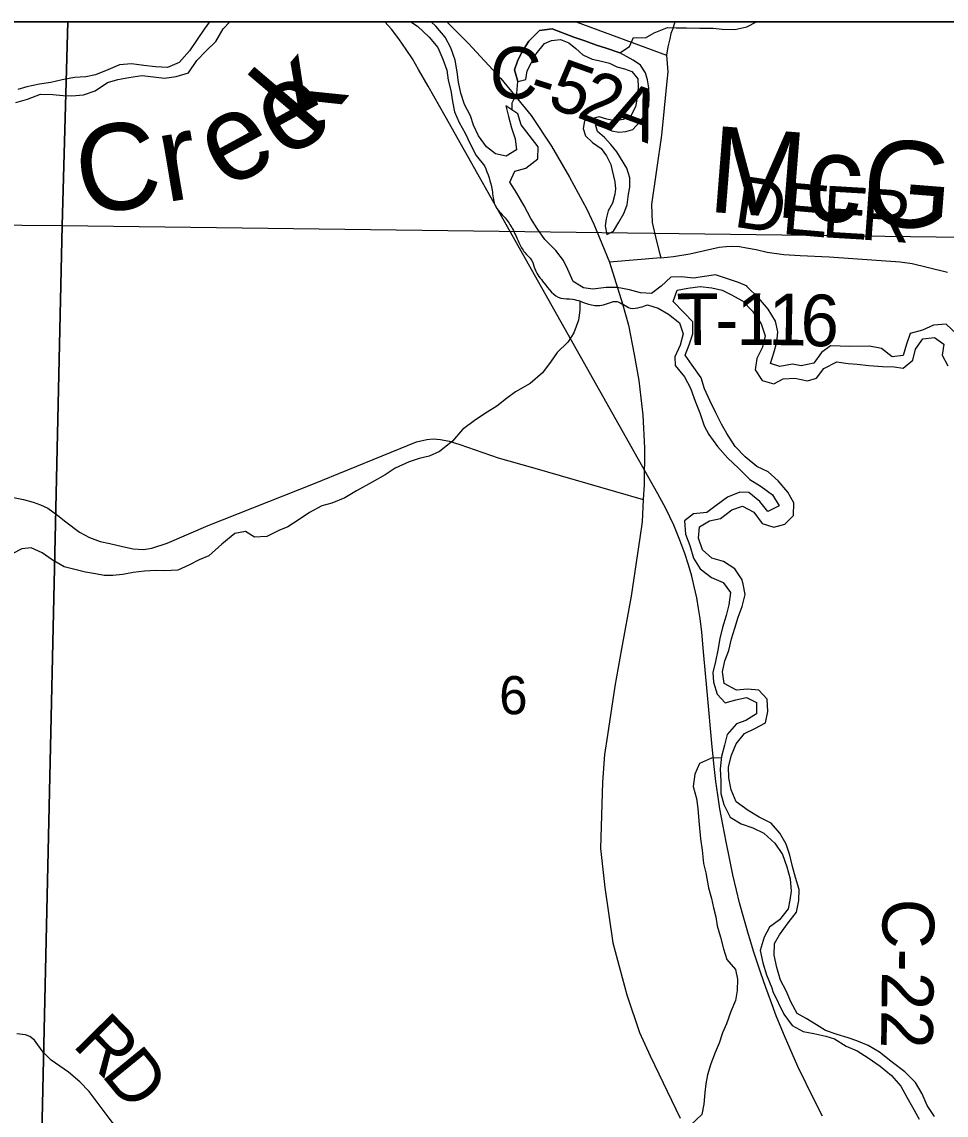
# Model space of a CAD drawing. Extents: x -1.2 to 34, y -8.5 to 22.
# Drawn here: x 4.454 to 5.468, y 19.699 to 20.9 of the extents above; entities that cross this region are included whole.
import ezdxf

# ---------------------------------------------------------------- set-up
doc = ezdxf.new("R2010")
doc.units = 0
for name, color, linetype in [('GM_X_County_Road', 7, 'Continuous'), ('GM_X_County_Road_Text', 7, 'Continuous'), ('GM_X_Major_River', 7, 'Continuous'), ('GM_X_Major_River_Text', 7, 'Continuous'), ('GM_X_Minor_Lake', 7, 'Continuous'), ('GM_X_Minor_River', 7, 'Continuous'), ('GM_X_Rail_Line', 7, 'Continuous'), ('GM_X_Section', 7, 'Continuous'), ('GM_X_Section_Text', 7, 'Continuous'), ('GM_X_State_Route', 7, 'Continuous'), ('GM_X_Township_Road', 7, 'Continuous'), ('GM_X_Township_Road_Text', 7, 'Continuous'), ('GM_X_Unincorporated_Text', 7, 'Continuous'), ('SH_Cut_Line', 7, 'Continuous'), ('SH_Data', 7, 'Continuous')]:
    doc.layers.add(name, color=color, linetype=linetype)

msp = doc.modelspace()

# ---------------------------------------------------------------- linework, layer by layer
at = {"layer": 'GM_X_County_Road'}
msp.add_line((5.0623, 20.9), (5.1613, 20.8632), dxfattribs=at)
for points in [[(5.1707, 20.9), (5.1707, 20.8998), (5.1681, 20.8917), (5.1663, 20.887), (5.1649, 20.8814), (5.1627, 20.8726), (5.1613, 20.8632), (5.1629, 20.8449), (5.1619, 20.8347), (5.156, 20.7754), (5.1449, 20.6994), (5.1458, 20.6794), (5.1503, 20.6592), (5.154, 20.6446)], [(5.154, 20.6446), (5.155, 20.6407), (5.0987, 20.6359)]]:
    msp.add_lwpolyline(points, dxfattribs=at)
at = {"layer": 'GM_X_Major_River'}
for points in [[(4.447, 20.8112), (4.4598, 20.8149), (4.4742, 20.8204), (4.4875, 20.8202), (4.4989, 20.8189), (4.5084, 20.8187), (4.5213, 20.8197), (4.5342, 20.8241), (4.5477, 20.8334), (4.5591, 20.8366), (4.5712, 20.8387), (4.5852, 20.8412), (4.5982, 20.8395), (4.6103, 20.8382), (4.6232, 20.84), (4.6365, 20.844), (4.6458, 20.8574), (4.6555, 20.8678), (4.6667, 20.8783), (4.6748, 20.8924), (4.6819, 20.9)], [(4.6598, 20.9), (4.6539, 20.8921), (4.6461, 20.8806), (4.6376, 20.8683), (4.6264, 20.8552), (4.6136, 20.8497), (4.6003, 20.8506), (4.5877, 20.8519), (4.574, 20.8539), (4.5607, 20.8526), (4.5482, 20.8474), (4.5346, 20.8419), (4.524, 20.8394), (4.5115, 20.8389), (4.4979, 20.8364), (4.4854, 20.8335), (4.4729, 20.8314), (4.4592, 20.8285), (4.4494, 20.8257)], [(4.8806, 20.9), (4.888, 20.8952), (4.9008, 20.8833), (4.9105, 20.8717), (4.916, 20.8589), (4.9204, 20.8468), (4.9217, 20.8359), (4.9246, 20.8245), (4.9263, 20.8124), (4.9288, 20.8011), (4.9339, 20.7894), (4.9402, 20.7778), (4.9461, 20.7653), (4.9524, 20.7533), (4.9617, 20.7417)], [(5.145, 20.6014), (5.1328, 20.6023), (5.1206, 20.6055), (5.1072, 20.608), (5.0951, 20.6081), (5.0807, 20.6064), (5.0704, 20.6077), (5.0589, 20.6147), (5.0529, 20.6279), (5.0482, 20.6377), (5.04, 20.6489), (5.0277, 20.6609), (5.0195, 20.6729), (5.0125, 20.6841), (5.005, 20.698), (4.9972, 20.7116), (4.9894, 20.724), (4.9949, 20.7358), (5.007, 20.7394), (5.0201, 20.7495), (5.0206, 20.7628), (5.0105, 20.7755), (5.002, 20.7868), (4.998, 20.7988), (4.9849, 20.8077), (4.9881, 20.796), (4.9914, 20.7835), (4.9954, 20.7715), (4.9967, 20.7594), (4.9855, 20.7523), (4.9736, 20.7548), (4.9636, 20.7626), (4.9551, 20.7746), (4.9495, 20.7866), (4.9463, 20.7968), (4.9397, 20.8092), (4.9356, 20.8217), (4.9332, 20.8338), (4.9314, 20.8451), (4.9293, 20.858), (4.9245, 20.8716), (4.9183, 20.8832), (4.9082, 20.8952), (4.9032, 20.9)], [(5.2501, 20.6096), (5.2406, 20.6136), (5.2283, 20.6176), (5.2153, 20.6219), (5.1911, 20.6185), (5.1777, 20.6198), (5.1663, 20.6196), (5.1555, 20.6095), (5.145, 20.6014)], [(5.2445, 20.287), (5.2363, 20.2991), (5.224, 20.3072), (5.2111, 20.3108), (5.201, 20.3201), (5.1966, 20.3329), (5.1976, 20.3451), (5.2085, 20.3517), (5.2206, 20.3542), (5.233, 20.3639), (5.2447, 20.3679), (5.2573, 20.3612), (5.2663, 20.3489), (5.2793, 20.3449), (5.2914, 20.3481), (5.3007, 20.3578), (5.3013, 20.3715), (5.2946, 20.3831), (5.2841, 20.3958), (5.273, 20.4055), (5.2607, 20.4114), (5.2476, 20.4221), (5.2368, 20.4333), (5.2278, 20.4476), (5.2219, 20.4578), (5.2156, 20.4705), (5.2089, 20.4841), (5.203, 20.4969), (5.1994, 20.509), (5.1896, 20.5228), (5.1819, 20.5337), (5.1862, 20.5452), (5.1902, 20.5574), (5.1904, 20.5703), (5.1803, 20.5807), (5.1687, 20.5927), (5.173, 20.6053), (5.1848, 20.6074), (5.1985, 20.6091), (5.211, 20.6078), (5.2225, 20.6053), (5.232, 20.6006), (5.2447, 20.5936), (5.2559, 20.582), (5.2653, 20.5681), (5.2697, 20.5549), (5.2669, 20.5427), (5.2606, 20.5301), (5.2589, 20.5176), (5.2663, 20.5059), (5.2793, 20.5023), (5.2895, 20.5078), (5.3024, 20.5084), (5.3161, 20.5056), (5.326, 20.5084), (5.3341, 20.5192), (5.3485, 20.5263), (5.3607, 20.5246), (5.3706, 20.524), (5.3835, 20.5223), (5.3984, 20.5214), (5.4113, 20.5209), (5.4212, 20.5195), (5.4317, 20.5284), (5.4349, 20.5402), (5.4427, 20.5517), (5.4556, 20.5531), (5.466, 20.546), (5.4639, 20.5339), (5.4702, 20.5222)], [(5.4799, 20.5573), (5.4683, 20.5677), (5.4546, 20.5667), (5.4425, 20.5612), (5.4289, 20.5576), (5.4249, 20.5457), (5.4213, 20.5335), (5.4092, 20.5318), (5.3973, 20.5411), (5.3843, 20.5435), (5.3619, 20.5432), (5.352, 20.5438), (5.3413, 20.544), (5.3316, 20.5366), (5.323, 20.5251), (5.3094, 20.5222), (5.2999, 20.5239), (5.2858, 20.5214), (5.2755, 20.5247), (5.2791, 20.5365), (5.2827, 20.5479), (5.2837, 20.5593), (5.2812, 20.571), (5.273, 20.5842), (5.2629, 20.5965), (5.2494, 20.6096), (5.2501, 20.6096)], [(5.1404, 20.589), (5.1521, 20.5856), (5.1636, 20.5789), (5.1756, 20.5693), (5.1796, 20.5572), (5.1763, 20.5446), (5.1705, 20.532), (5.171, 20.5225), (5.1811, 20.5098), (5.1878, 20.4974), (5.193, 20.4834), (5.1981, 20.4706), (5.2029, 20.4563), (5.208, 20.4465), (5.2174, 20.4334), (5.2286, 20.4207), (5.2406, 20.4095), (5.2529, 20.3972), (5.2652, 20.3894), (5.2779, 20.3802), (5.285, 20.3681), (5.2725, 20.3619), (5.264, 20.3731), (5.2517, 20.3828), (5.2418, 20.3834), (5.2282, 20.3778), (5.2158, 20.3685), (5.2057, 20.3611), (5.1909, 20.3594), (5.1811, 20.3516), (5.1821, 20.3372), (5.1869, 20.3248), (5.1909, 20.3108), (5.1983, 20.2992), (5.2107, 20.2895), (5.2237, 20.284), (5.2318, 20.2732), (5.2298, 20.2595), (5.2269, 20.2477), (5.223, 20.2347), (5.2198, 20.2225), (5.2177, 20.2096), (5.2152, 20.1974), (5.2124, 20.1852), (5.213, 20.1746), (5.217, 20.1614), (5.2259, 20.1517), (5.2376, 20.1553), (5.2494, 20.1578), (5.2601, 20.1523), (5.2603, 20.1397), (5.2486, 20.1323), (5.2381, 20.1288), (5.228, 20.1172), (5.2251, 20.1054), (5.2219, 20.0928), (5.2203, 20.0795), (5.2209, 20.0659), (5.2211, 20.0522), (5.2243, 20.0401), (5.2314, 20.0262), (5.2433, 20.0188), (5.2563, 20.0145), (5.2682, 20.0086), (5.2802, 19.9978), (5.2887, 19.9851), (5.2935, 19.9715), (5.2972, 19.9586), (5.2982, 19.945), (5.2968, 19.9351), (5.2951, 19.9256), (5.2854, 19.9133), (5.2745, 19.9052), (5.2686, 19.8944), (5.2643, 19.8796), (5.2672, 19.8663), (5.2712, 19.8531), (5.2771, 19.8388)], [(5.4555, 19.6972), (5.4477, 19.7096), (5.4421, 19.7221), (5.4347, 19.7348), (5.4231, 19.7464), (5.4096, 19.7568), (5.3954, 19.7679), (5.3827, 19.7753), (5.3705, 19.7804), (5.3609, 19.7837), (5.3487, 19.7876), (5.3361, 19.792), (5.3261, 19.7979), (5.3146, 19.8049), (5.305, 19.8104), (5.2979, 19.8232), (5.2928, 19.8353), (5.2865, 19.8473), (5.2824, 19.8609), (5.2796, 19.8745), (5.2801, 19.8874), (5.2856, 19.897), (5.2949, 19.91), (5.3042, 19.922), (5.3067, 19.9345), (5.3069, 19.9467), (5.3032, 19.9599), (5.2996, 19.972), (5.2967, 19.9844), (5.2927, 19.9965), (5.2857, 20.0085), (5.2764, 20.0198), (5.2633, 20.0264), (5.2511, 20.0334), (5.238, 20.043), (5.2324, 20.0562), (5.2299, 20.0694), (5.2293, 20.0816), (5.2329, 20.0945), (5.238, 20.1067), (5.247, 20.1183), (5.2583, 20.1238), (5.27, 20.1297), (5.2728, 20.1422), (5.2718, 20.1559), (5.2629, 20.1656), (5.2503, 20.1669), (5.2382, 20.1659), (5.2248, 20.1729), (5.223, 20.1858), (5.2255, 20.198), (5.2299, 20.2094), (5.2327, 20.222), (5.2363, 20.2338), (5.2399, 20.246), (5.2446, 20.2578), (5.2478, 20.2708), (5.2457, 20.2821), (5.2445, 20.287)], [(5.2771, 19.8388), (5.2783, 19.8347), (5.2901, 19.8098), (5.2995, 19.7975), (5.3114, 19.7908), (5.3232, 19.7884), (5.3362, 19.7855), (5.3457, 19.7827), (5.3588, 19.7745), (5.3706, 19.7694), (5.3829, 19.762), (5.396, 19.7528), (5.4084, 19.7424), (5.4188, 19.7308), (5.4251, 19.7187), (5.4314, 19.7075), (5.4388, 19.6943)]]:
    msp.add_lwpolyline(points, dxfattribs=at)
msp.add_spline([(4.9617, 20.7417), (4.9699, 20.7151), (4.973, 20.6988), (4.9842, 20.6845), (4.9923, 20.6725), (4.9993, 20.6577), (5.0059, 20.6465), (5.0133, 20.638), (5.0171, 20.6279), (5.0268, 20.6132), (5.0454, 20.5965), (5.0582, 20.5953), (5.0757, 20.5899), (5.09, 20.5887), (5.1071, 20.5926), (5.1214, 20.5856), (5.1326, 20.5864), (5.1404, 20.589)], degree=3, dxfattribs=at)
at = {"layer": 'GM_X_Minor_Lake'}
for points in [[(5.1102, 20.8659), (5.0953, 20.871), (5.0847, 20.8744), (5.0717, 20.8792), (5.0595, 20.8833), (5.0454, 20.8888), (5.0359, 20.8922), (5.0219, 20.8905), (5.0102, 20.8787), (5.0038, 20.8684), (4.9982, 20.8577), (4.9945, 20.8474), (4.998, 20.8345)], [(4.998, 20.8345), (5.0068, 20.8365), (5.0086, 20.846), (5.013, 20.8552), (5.0183, 20.8647), (5.0273, 20.8761), (5.0352, 20.8796), (5.0451, 20.8805), (5.0543, 20.8768), (5.0619, 20.8708), (5.0696, 20.8636), (5.0799, 20.8588), (5.0901, 20.8566), (5.0989, 20.8544), (5.1069, 20.8507), (5.1153, 20.8485), (5.1233, 20.8455), (5.1298, 20.8372), (5.1303, 20.8281), (5.1296, 20.819), (5.1274, 20.8065), (5.1222, 20.7969), (5.1139, 20.7927), (5.1048, 20.7911), (5.096, 20.7929), (5.0876, 20.7955), (5.0789, 20.7935), (5.0714, 20.7912), (5.0699, 20.7828), (5.0726, 20.7749), (5.0803, 20.7674), (5.0895, 20.761), (5.0956, 20.7527), (5.1003, 20.7432), (5.1018, 20.7368), (5.1046, 20.7243), (5.1054, 20.7164), (5.1047, 20.7107), (5.1022, 20.7008), (5.0973, 20.6924), (5.0951, 20.6836), (5.094, 20.6757), (5.096, 20.6662), (5.1032, 20.6701), (5.1092, 20.68), (5.1144, 20.6895), (5.1181, 20.699), (5.1188, 20.7047), (5.1195, 20.7108), (5.121, 20.7184), (5.1213, 20.7286), (5.1178, 20.7392), (5.107, 20.7573), (5.1004, 20.7653), (5.0935, 20.7728), (5.0855, 20.7795), (5.0835, 20.7871), (5.0927, 20.7838), (5.1015, 20.7801), (5.1091, 20.7786), (5.1167, 20.7794), (5.1246, 20.7818), (5.1318, 20.7898), (5.1385, 20.7986), (5.1419, 20.8077), (5.1425, 20.8176), (5.1421, 20.8274), (5.1405, 20.8362), (5.1385, 20.8441), (5.1327, 20.8524), (5.1247, 20.858), (5.1102, 20.8659)]]:
    msp.add_lwpolyline(points, dxfattribs=at)
at = {"layer": 'GM_X_Minor_River'}
for points in [[(4.9919, 20.8029), (4.9918, 20.811), (4.997, 20.8213), (4.998, 20.8345), (4.9945, 20.8474), (4.9982, 20.8577), (5.0038, 20.8684), (5.0102, 20.8787), (5.0219, 20.8905), (5.0359, 20.8922), (5.0454, 20.8888), (5.0595, 20.8833), (5.0717, 20.8792), (5.0847, 20.8744), (5.0953, 20.871), (5.1102, 20.8659), (5.1208, 20.8728), (5.1252, 20.8827), (5.1382, 20.8824), (5.148, 20.8878), (5.1624, 20.8936), (5.1719, 20.8933), (5.1833, 20.8934), (5.1981, 20.8932), (5.2125, 20.8929), (5.2224, 20.8919), (5.2365, 20.8916), (5.2497, 20.8944), (5.2601, 20.9)], [(5.0662, 20.5928), (5.0664, 20.5832), (5.0649, 20.5722), (5.0597, 20.5582), (5.053, 20.5482), (5.0413, 20.5367), (5.0349, 20.5272), (5.0252, 20.5142), (5.0116, 20.5027), (4.9957, 20.4935), (4.9859, 20.4862), (4.975, 20.4778), (4.9644, 20.4712), (4.9516, 20.4628), (4.9376, 20.452), (4.9263, 20.4394), (4.912, 20.4279), (4.9007, 20.4229), (4.89, 20.4201), (4.8787, 20.4166), (4.8635, 20.4096), (4.8526, 20.4023), (4.8382, 20.3942), (4.8212, 20.3846), (4.8084, 20.3769), (4.794, 20.3711), (4.783, 20.3683), (4.7694, 20.361), (4.7581, 20.3533), (4.7456, 20.3453), (4.7358, 20.341), (4.7225, 20.3344), (4.7089, 20.3339), (4.6993, 20.3399), (4.6876, 20.3379), (4.6732, 20.326), (4.6589, 20.3134), (4.6483, 20.3088), (4.637, 20.303), (4.6249, 20.2976), (4.6104, 20.2967), (4.6009, 20.2973), (4.5884, 20.2965), (4.5759, 20.2952), (4.5645, 20.2929), (4.5535, 20.2916), (4.544, 20.2919), (4.5345, 20.2934), (4.5235, 20.2955), (4.5105, 20.2985), (4.5002, 20.3014), (4.4869, 20.3089), (4.4758, 20.3167), (4.464, 20.322), (4.4537, 20.3211), (4.4431, 20.3157)], [(5.2218, 20.0915), (5.2109, 20.0909), (5.1976, 20.0851), (5.1924, 20.0733), (5.1906, 20.06), (5.1942, 20.0468), (5.1958, 20.0358), (5.197, 20.0222), (5.1987, 20.0024), (5.2004, 19.9899), (5.202, 19.9755), (5.2044, 19.9649), (5.2076, 19.9486), (5.2107, 19.9369), (5.2131, 19.9267), (5.2155, 19.9168), (5.2171, 19.907), (5.2206, 19.8945), (5.2241, 19.8816), (5.2276, 19.8699), (5.2372, 19.859), (5.2392, 19.8484), (5.239, 19.8359), (5.2372, 19.8248), (5.2319, 19.8127), (5.2271, 19.799), (5.223, 19.7894), (5.2193, 19.778), (5.2149, 19.7677), (5.21, 19.7552), (5.2063, 19.743), (5.2045, 19.7331), (5.2035, 19.7236), (5.2025, 19.7111), (5.2003, 19.6997), (5.1878, 19.6878)]]:
    msp.add_lwpolyline(points, dxfattribs=at)
at = {"layer": 'GM_X_Rail_Line'}
msp.add_lwpolyline([(5.3325, 19.6978), (5.3223, 19.7178), (5.3146, 19.7337), (5.3057, 19.7522), (5.2969, 19.7725), (5.29, 19.7886), (5.2819, 19.808), (5.2755, 19.8252), (5.2704, 19.8392), (5.2645, 19.856), (5.2572, 19.8779), (5.2513, 19.8975), (5.2464, 19.9153), (5.2417, 19.9321), (5.2384, 19.9461), (5.2343, 19.9627), (5.2304, 19.981), (5.2268, 19.999), (5.2231, 20.0183), (5.22, 20.0354), (5.2179, 20.0506), (5.2157, 20.0655), (5.2137, 20.0819), (5.2116, 20.1036), (5.206, 20.1642), (5.202, 20.2077), (5.2001, 20.2295), (5.1983, 20.2446), (5.1966, 20.2553), (5.1946, 20.2672), (5.1918, 20.2796), (5.1892, 20.2911), (5.1856, 20.3035), (5.1816, 20.3158), (5.176, 20.3306), (5.1693, 20.3469), (5.1605, 20.3652), (5.1518, 20.3814), (4.9185, 20.7962), (4.8996, 20.8293), (4.8892, 20.8475), (4.8824, 20.8593), (4.8757, 20.8695), (4.8677, 20.8812), (4.8593, 20.892), (4.8523, 20.9)], dxfattribs=at)
at = {"layer": 'GM_X_Section'}
for points in [[(4.504, 20.9), (3.4869, 20.9), (3.4838, 20.6845), (4.4978, 20.6761)], [(5.5189, 20.9), (4.504, 20.9), (4.4978, 20.6761), (5.5138, 20.6632), (5.5152, 20.7534)], [(3.4838, 20.6845), (4.4978, 20.6761), (4.4756, 19.6778), (3.4745, 19.7148)], [(5.5138, 20.6632), (5.4939, 19.7699), (5.4956, 19.6725), (4.4756, 19.6778), (4.4978, 20.6761)]]:
    msp.add_lwpolyline(points, close=True, dxfattribs=at)
at = {"layer": 'GM_X_State_Route'}
msp.add_lwpolyline([(4.9203, 20.9), (4.9254, 20.8949), (4.9439, 20.8761), (4.9794, 20.8378), (5.0129, 20.7971), (5.0353, 20.7634), (5.0549, 20.7293), (5.0739, 20.6941), (5.0817, 20.6776), (5.0905, 20.6563), (5.0987, 20.6359), (5.113, 20.5902), (5.1197, 20.5669), (5.1259, 20.5347), (5.1309, 20.506), (5.1353, 20.4677), (5.1373, 20.432), (5.137, 20.3915), (5.1357, 20.3754), (5.1347, 20.3505), (5.1323, 20.3331), (5.1226, 20.2691), (5.1119, 20.2112), (5.1045, 20.1702), (5.0967, 20.1164), (5.0935, 20.095), (5.0912, 20.0645), (5.089, 19.9919), (5.0938, 19.9489), (5.1024, 19.8883), (5.1179, 19.8311), (5.1318, 19.7898), (5.1434, 19.764), (5.1765, 19.6954)], dxfattribs=at)
at = {"layer": 'GM_X_Township_Road'}
for points in [[(5.155, 20.6407), (5.1692, 20.6421), (5.1871, 20.6452), (5.2191, 20.6524), (5.2268, 20.6532), (5.2338, 20.6535), (5.2416, 20.6532), (5.2492, 20.6517), (5.2599, 20.6497), (5.2719, 20.6471), (5.2902, 20.6443), (5.3081, 20.6433), (5.3401, 20.6417), (5.418, 20.6365), (5.4311, 20.6344), (5.4477, 20.6305), (5.47, 20.6248)], [(4.4388, 20.3784), (4.4556, 20.3751), (4.4661, 20.3723), (4.4741, 20.3695), (4.4822, 20.3658), (4.4932, 20.3576), (4.5021, 20.3508), (4.517, 20.3395), (4.5279, 20.3334), (4.5397, 20.3292), (4.5502, 20.3269), (4.5642, 20.3234), (4.576, 20.3212), (4.5872, 20.3204), (4.5962, 20.3218), (4.613, 20.3274), (4.6582, 20.3466), (4.7738, 20.3926), (4.8868, 20.4386), (4.8982, 20.4412), (4.9054, 20.4418), (4.9132, 20.4412), (4.9228, 20.4393), (4.9344, 20.4358), (4.9764, 20.421), (5.0144, 20.4105), (5.1357, 20.3754)], [(4.716, 19.4732), (4.6649, 19.5231), (4.5971, 19.6063), (4.5868, 19.6221), (4.5775, 19.643), (4.5642, 19.6764), (4.5494, 19.6957), (4.5275, 19.725), (4.5174, 19.7356), (4.5048, 19.7459), (4.4859, 19.7592), (4.4772, 19.7681), (4.4711, 19.7762), (4.4674, 19.7811), (4.4625, 19.7853), (4.4575, 19.787), (4.4482, 19.7883)]]:
    msp.add_lwpolyline(points, dxfattribs=at)
at = {"layer": 'GM_X_Unincorporated_Text'}
msp.add_lwpolyline([(6.665, 17.7216), (6.6751, 17.7216), (6.7322, 17.7204), (7.1254, 17.7122), (7.3722, 17.707), (7.8111, 17.6977), (7.9782, 17.6941), (8.3326, 17.6871), (8.3461, 18.0704), (8.364, 18.7117), (8.3686, 18.968), (8.382, 19.7108), (8.4089, 20.6815), (8.4143, 20.9), (2.465, 20.9)], dxfattribs=at)
at = {"layer": 'SH_Cut_Line'}
msp.add_lwpolyline([(6.665, 17.7216), (6.6751, 17.7216), (6.7322, 17.7204), (7.1254, 17.7122), (7.3722, 17.707), (7.8111, 17.6977), (7.9782, 17.6941), (8.3326, 17.6871), (8.9, 17.6758), (8.9, 20.9), (2.465, 20.9)], dxfattribs=at)
at = {"layer": 'SH_Data'}
msp.add_line((2.1, 20.9), (8.9, 20.9), dxfattribs=at)

# ---------------------------------------------------------------- texts
at = {"layer": 'GM_X_County_Road_Text'}
for s, height, rotation, p in [('C', 0.0568, 351.9962, (4.9638, 20.8199)), ('5', 0.0568, 340.4292, (5.0288, 20.8072)), ('2', 0.0568, 339.7555, (5.0613, 20.7956)), ('-', 0.0568, 342.3045, (5.0072, 20.814)), ('A', 0.0568, 339.6669, (5.0939, 20.7836)), ('C-22', 0.05682, 269.3129, (5.3989, 19.937))]:
    msp.add_text(s, height=height, rotation=rotation, dxfattribs=at).set_placement(p)
at = {"layer": 'GM_X_Major_River_Text'}
for s, height, rotation, p in [('k', 0.0947, 49.5516, (4.772, 20.771)), ('ee', 0.0947, 28.5521, (4.6766, 20.715)), ('Cr', 0.09471, 9.5544, (4.521, 20.6863)), ('McGuire', 0.09471, 355.4839, (5.2055, 20.6915))]:
    msp.add_text(s, height=height, rotation=rotation, dxfattribs=at).set_placement(p)
at = {"layer": 'GM_X_Section_Text'}
msp.add_text('6', height=0.0419, rotation=0, dxfattribs=at).set_placement((4.9777, 20.1393))
at = {"layer": 'GM_X_Township_Road_Text'}
for s, rotation, p in [('D', 351.466, (5.2338, 20.6752)), ('E', 355.0192, (5.287, 20.6673)), ('E', 356.607, (5.331, 20.6635)), ('R', 355.8885, (5.3732, 20.661)), ('T', 0.3857, (5.1725, 20.5447)), ('1', 359.7684, (5.2382, 20.5451)), ('1', 359.0711, (5.273, 20.545)), ('6', 357.8972, (5.3077, 20.5444)), ('-', 0.2342, (5.215, 20.545)), ('R', 314.5915, (4.5081, 19.7754)), ('D', 309.2774, (4.5399, 19.7432))]:
    msp.add_text(s, height=0.0568, rotation=rotation, dxfattribs=at).set_placement(p)

doc.saveas('drawing.dxf')
